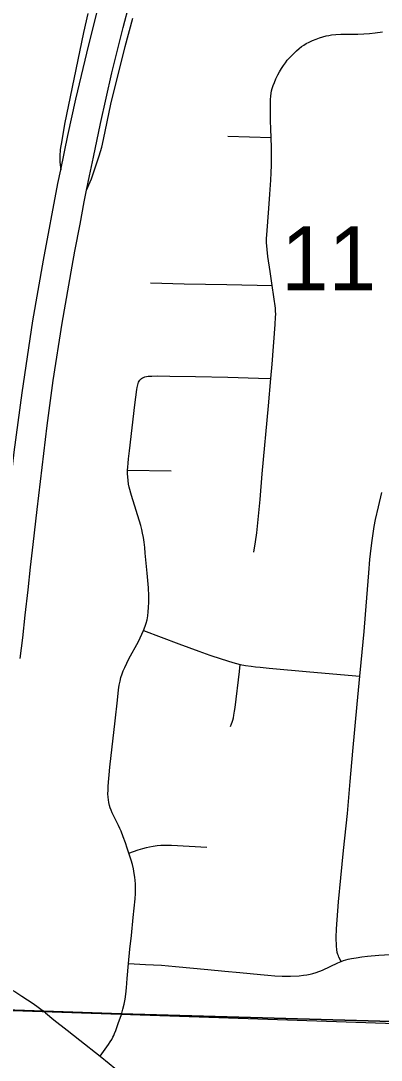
# Model space of a CAD drawing. Extents: x 0 to 34, y 0 to 22.
# Drawn here: x 3.886 to 4.122, y 14.689 to 15.369 of the extents above; entities that cross this region are included whole.
import ezdxf

# ---------------------------------------------------------------- set-up
doc = ezdxf.new("R2010")
doc.units = 0
for name, color, linetype in [('GM_X_City_Street', 7, 'Continuous'), ('GM_X_Corporation', 7, 'Continuous'), ('GM_X_County_Road', 7, 'Continuous'), ('GM_X_Interchange_Ramps', 7, 'Continuous'), ('GM_X_Interstate_Route', 7, 'Continuous'), ('GM_X_Section_Text', 7, 'Continuous'), ('GM_X_Township_Road', 7, 'Continuous')]:
    doc.layers.add(name, color=color, linetype=linetype)

msp = doc.modelspace()

# ---------------------------------------------------------------- linework, layer by layer
at = {"layer": 'GM_X_City_Street'}
for p, q in [((4.02119, 15.29365), (4.04975, 15.29287)), ((3.95564, 15.075), (3.98411, 15.07475))]:
    msp.add_line(p, q, dxfattribs=at)
for points in [[(4.03835, 15.02145), (4.0394, 15.02815), (4.04024, 15.03411), (4.04105, 15.04051), (4.04246, 15.05581), (4.04389, 15.0727), (4.04786, 15.11724), (4.04944, 15.13517), (4.05032, 15.14445), (4.05228, 15.17049), (4.05257, 15.17515), (4.05266, 15.17728), (4.05261, 15.17925), (4.05247, 15.1812), (4.05038, 15.19597), (4.04894, 15.20523), (4.04757, 15.21502), (4.04706, 15.21951), (4.0467, 15.22424), (4.04663, 15.2267), (4.04674, 15.2291), (4.0482, 15.2464), (4.04885, 15.25579), (4.04943, 15.26491), (4.04967, 15.26984), (4.04984, 15.27469), (4.04992, 15.27938), (4.04992, 15.2862), (4.04975, 15.29287), (4.04947, 15.29835), (4.04925, 15.30411), (4.04914, 15.31117), (4.0493, 15.31776), (4.04947, 15.31993), (4.04974, 15.32196), (4.05, 15.32342), (4.05036, 15.32487), (4.05099, 15.32683), (4.05177, 15.32887), (4.05284, 15.33139), (4.05405, 15.33388), (4.0551, 15.33591), (4.05646, 15.33813), (4.05777, 15.34011), (4.05901, 15.34183), (4.06024, 15.3434), (4.06168, 15.345), (4.06299, 15.3464), (4.06455, 15.34791), (4.06636, 15.34968), (4.06797, 15.35108), (4.06962, 15.35238), (4.071, 15.35338), (4.07261, 15.35437), (4.07458, 15.35539), (4.07676, 15.35634), (4.07906, 15.35728), (4.08141, 15.35815), (4.08362, 15.35885), (4.08569, 15.35938), (4.08737, 15.35971), (4.08926, 15.36), (4.09213, 15.36028), (4.09539, 15.36043), (4.10654, 15.36061), (4.11034, 15.36074), (4.11408, 15.36099), (4.1179, 15.3614), (4.1227, 15.36204)], [(3.97067, 15.19762), (3.99273, 15.19711), (4.02065, 15.19662), (4.05038, 15.19597)], [(3.95624, 14.75219), (3.95713, 14.76138), (3.95815, 14.77051), (3.95935, 14.78217), (3.95998, 14.78829), (3.96055, 14.79435), (3.96081, 14.79782), (3.96089, 14.79946), (3.96089, 14.80111), (3.96089, 14.80263), (3.96081, 14.80424), (3.96065, 14.80649), (3.96036, 14.80871), (3.96003, 14.81106), (3.95946, 14.81405), (3.95879, 14.81687), (3.95798, 14.81972), (3.9565, 14.82431), (3.95539, 14.82758), (3.95419, 14.83107), (3.95272, 14.83506), (3.95132, 14.83863), (3.95056, 14.84046), (3.94971, 14.84237), (3.9482, 14.84553), (3.94647, 14.84891), (3.94561, 14.85066), (3.9448, 14.85258), (3.94425, 14.85408), (3.94375, 14.85561), (3.9433, 14.85743), (3.94306, 14.85918), (3.94285, 14.86108), (3.94279, 14.86321), (3.94281, 14.86556), (3.94291, 14.86825), (3.94406, 14.88067), (3.94741, 14.9109), (3.94891, 14.92447), (3.94969, 14.93135), (3.95014, 14.93442), (3.95068, 14.93688), (3.9513, 14.93926), (3.95209, 14.94174), (3.95278, 14.94362), (3.95372, 14.94585), (3.95652, 14.95147), (3.96271, 14.96292), (3.96609, 14.97002), (3.96724, 14.97297), (3.96782, 14.9749), (3.96835, 14.97718), (3.96885, 14.97965), (3.96917, 14.98228), (3.96942, 14.98524), (3.96958, 14.98862), (3.96958, 14.99085), (3.96952, 14.99288), (3.96924, 14.99803), (3.96886, 15.00277), (3.96848, 15.00769), (3.96721, 15.02067), (3.96688, 15.02448), (3.96647, 15.02805), (3.96605, 15.03095), (3.96549, 15.03382), (3.96494, 15.03626), (3.96423, 15.03882), (3.95815, 15.05839), (3.95674, 15.06387), (3.9563, 15.06592), (3.95597, 15.06822), (3.95572, 15.07069), (3.95565, 15.07265), (3.95564, 15.075), (3.95572, 15.07708), (3.95593, 15.07977), (3.95622, 15.08256), (3.95682, 15.08763), (3.96039, 15.11793), (3.96172, 15.12784), (3.962, 15.12931), (3.96233, 15.13088), (3.96261, 15.13189), (3.96288, 15.13269), (3.96325, 15.13344), (3.96366, 15.13402), (3.96417, 15.13453), (3.96476, 15.13504), (3.96535, 15.13544), (3.966, 15.13577), (3.96688, 15.13612), (3.96799, 15.13642), (3.96921, 15.13663), (3.97047, 15.1367), (3.97155, 15.13673)], [(3.97155, 15.13673), (3.97517, 15.13676), (3.9834, 15.13672), (4.00019, 15.1364), (4.02133, 15.13589), (4.04131, 15.13538), (4.04944, 15.13517)], [(4.09553, 14.75337), (4.09409, 14.75626), (4.09372, 14.75707), (4.09339, 14.7579), (4.09316, 14.7586), (4.09298, 14.75939), (4.0927, 14.76133), (4.09252, 14.7635), (4.09232, 14.76919), (4.09247, 14.7749), (4.09384, 14.79254), (4.09523, 14.80826), (4.09716, 14.82612), (4.09964, 14.85021), (4.1015, 14.87125), (4.10319, 14.89104), (4.10612, 14.92191), (4.10775, 14.9402), (4.10862, 14.9491), (4.11055, 14.96952), (4.11154, 14.98064), (4.11364, 15.00787), (4.11439, 15.01662), (4.11513, 15.0241), (4.11579, 15.02903), (4.11645, 15.03356), (4.11718, 15.03815), (4.1181, 15.04284), (4.1199, 15.05115), (4.12207, 15.06037)], [(3.96609, 14.97002), (3.98913, 14.96148), (4.00224, 14.95657), (4.00959, 14.95392), (4.0169, 14.95148), (4.02459, 14.94915), (4.02694, 14.9485), (4.02945, 14.9479), (4.03286, 14.94727), (4.03665, 14.94668), (4.03935, 14.94634), (4.0424, 14.94603), (4.04836, 14.94546), (4.075, 14.94308), (4.10775, 14.9402)], [(4.02303, 14.90723), (4.02378, 14.90909), (4.02415, 14.91016), (4.02452, 14.91143), (4.02492, 14.91298), (4.02532, 14.91477), (4.02574, 14.91722), (4.02609, 14.91979), (4.02883, 14.94332), (4.02945, 14.9479)], [(3.9565, 14.82431), (3.95954, 14.82546), (3.96258, 14.82645), (3.96567, 14.82735), (3.96809, 14.82797), (3.96996, 14.8284), (3.97241, 14.82887), (3.97493, 14.82926), (3.97734, 14.82948), (3.97994, 14.82965), (3.98215, 14.82965), (3.98431, 14.82963), (3.99603, 14.82894), (4.00743, 14.82825)], [(3.95624, 14.75219), (3.96734, 14.75153), (3.97793, 14.7509), (3.98709, 14.75024), (4.00824, 14.74822), (4.01934, 14.74699), (4.02922, 14.7461), (4.04279, 14.74493), (4.04739, 14.74442), (4.05211, 14.74405), (4.05683, 14.7439), (4.06244, 14.74384), (4.06794, 14.74407), (4.07095, 14.74438), (4.07308, 14.74471), (4.07512, 14.74513), (4.07706, 14.74561), (4.07921, 14.74629), (4.0832, 14.74781), (4.09332, 14.75252), (4.09553, 14.75337), (4.09708, 14.75399), (4.09856, 14.75447), (4.10012, 14.7549), (4.10222, 14.75535), (4.10538, 14.75586), (4.10908, 14.75638), (4.11282, 14.75681), (4.12026, 14.75747), (4.12774, 14.75788)]]:
    msp.add_lwpolyline(points, dxfattribs=at)
at = {"layer": 'GM_X_Corporation'}
msp.add_lwpolyline([(4.68777, 15.72423), (4.60595, 14.69637), (3.48216, 14.73461), (3.56805, 15.74872)], close=True, dxfattribs=at)
for points in [[(3.53208, 15.37441), (3.52951, 15.35867), (3.52737, 15.35109), (3.52277, 15.33838), (3.5165, 15.24188), (3.51637, 15.17904), (3.49583, 14.91334), (3.47341, 14.73338), (3.47906, 14.73437), (3.5905, 14.72847), (3.63706, 14.72601), (3.71943, 14.72701), (3.74986, 14.72596), (3.84378, 14.72272), (3.8625, 14.72228), (3.90087, 14.72095), (3.95135, 14.71922), (4.34443, 14.70806), (4.61526, 14.69692)], [(4.61526, 14.69692), (4.34443, 14.70806), (3.95135, 14.71922), (3.90087, 14.72095), (3.8625, 14.72228), (3.84378, 14.72272), (3.74986, 14.72596), (3.71943, 14.72701), (3.63706, 14.72601), (3.5905, 14.72847), (3.47906, 14.73437), (3.47341, 14.73338), (3.459, 14.54458), (3.43805, 14.30587), (7.02308, 14.30587)]]:
    msp.add_lwpolyline(points, dxfattribs=at)
at = {"layer": 'GM_X_County_Road'}
for points in [[(3.7518, 14.73673), (3.76147, 14.73955), (3.77799, 14.74411), (3.79001, 14.74695), (3.80224, 14.74901), (3.81409, 14.75026), (3.82285, 14.75071), (3.83034, 14.75018), (3.83903, 14.74908), (3.84524, 14.74779), (3.84761, 14.7473), (3.85724, 14.7446), (3.86411, 14.74214), (3.8649, 14.74186), (3.87349, 14.73808), (3.87847, 14.73544), (3.88168, 14.73369), (3.88644, 14.73061), (3.89, 14.72833), (3.89375, 14.72589), (3.9011, 14.72042), (3.90178, 14.71984)], [(3.90178, 14.71984), (3.90724, 14.71518), (3.91602, 14.7085), (3.9244, 14.70189), (3.93763, 14.69137)], [(3.93763, 14.69137), (3.94365, 14.68655), (3.95088, 14.6806), (3.95675, 14.67555), (3.9629, 14.67048), (3.97107, 14.66346), (3.98073, 14.65529), (3.99578, 14.643), (4.00186, 14.63854), (4.0136, 14.63119), (4.0147, 14.63053)]]:
    msp.add_lwpolyline(points, dxfattribs=at)
at = {"layer": 'GM_X_Interchange_Ramps'}
for points in [[(3.92951, 15.37399), (3.92675, 15.36169), (3.91425, 15.30153), (3.91249, 15.29081), (3.91154, 15.28493), (3.91119, 15.28058), (3.91119, 15.2767), (3.91182, 15.27161)], [(3.92882, 15.2585), (3.93194, 15.26589), (3.9336, 15.27048), (3.93706, 15.28098), (3.93871, 15.28658), (3.93982, 15.29146), (3.94466, 15.31461), (3.95396, 15.35241), (3.95913, 15.37097)]]:
    msp.add_lwpolyline(points, dxfattribs=at)
at = {"layer": 'GM_X_Interstate_Route'}
for points in [[(3.91182, 15.27161), (3.91643, 15.29429), (3.92166, 15.31792), (3.93014, 15.35354), (3.94101, 15.39627)], [(3.88536, 14.95179), (3.88695, 14.96535), (3.8886, 14.98017), (3.89047, 14.99683), (3.8921, 15.01165), (3.89381, 15.02647), (3.89641, 15.04931), (3.90289, 15.10424), (3.90689, 15.13382), (3.91274, 15.1713), (3.91935, 15.20864), (3.92114, 15.21842), (3.92446, 15.23614), (3.92729, 15.25079), (3.92882, 15.2585), (3.93067, 15.26786), (3.93322, 15.28003), (3.93778, 15.30194), (3.94535, 15.3353), (3.95275, 15.36486), (3.95684, 15.3805)], [(3.85322, 14.30587), (3.85214, 14.32224), (3.84834, 14.37616), (3.8442, 14.4394), (3.84137, 14.48961), (3.84025, 14.52186), (3.83954, 14.56034), (3.83953, 14.60194), (3.84019, 14.63794), (3.84136, 14.67143), (3.84401, 14.72219), (3.84524, 14.74779), (3.8457, 14.75716), (3.84658, 14.77016), (3.84941, 14.80356), (3.8519, 14.82888), (3.86181, 14.91464), (3.87204, 15.00665), (3.88138, 15.08685), (3.8865, 15.12562), (3.89356, 15.1729), (3.90047, 15.21264), (3.91, 15.26267), (3.91182, 15.27161)]]:
    msp.add_lwpolyline(points, dxfattribs=at)
at = {"layer": 'GM_X_Township_Road'}
for points in [[(3.95158, 14.71869), (3.95255, 14.72216), (3.95344, 14.72549), (3.95408, 14.72868), (3.95449, 14.73199), (3.95493, 14.73617), (3.95539, 14.74231), (3.95624, 14.75219)], [(3.93763, 14.69137), (3.94312, 14.69911), (3.94428, 14.70087), (3.94522, 14.70238), (3.946, 14.70383), (3.94653, 14.70494), (3.94711, 14.70629), (3.94785, 14.70822), (3.94955, 14.71277), (3.95158, 14.71869)]]:
    msp.add_lwpolyline(points, dxfattribs=at)

# ---------------------------------------------------------------- texts
at = {"layer": 'GM_X_Section_Text'}
msp.add_text('11', height=0.041856, rotation=0.00001, dxfattribs=at).set_placement((4.05614, 15.1928))

doc.saveas('drawing.dxf')
